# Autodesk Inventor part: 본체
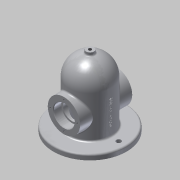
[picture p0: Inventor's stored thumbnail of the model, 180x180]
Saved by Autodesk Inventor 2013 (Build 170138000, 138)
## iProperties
Created: 2019-11
Part Number: 본체
Material: 알루미늄 6061
Document SubType Name: Modeling
Designer: Administrator
Density: 2.71 g/cm^3
Mass: 1186.55 g
Surface Area: 921.221 cm^2
Volume: 437.841 cm^3
Author: Administrator
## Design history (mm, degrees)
sketch "스케치1"
  geometry: C1 r 40 at (0, 0); 1 further point
  constraints: 1 centre point, 1 coincident
  dimensions: "d0" = 80 diameter of C1
extrude "돌출1" new body sketch "스케치1" distance "d2" = 90; taper "d3" = 0 deg
sketch "스케치2"
  geometry: L1 (40, 90)-(-40, 90) reference; L2 (0, 90)-(0, 130); L3 (-40, 90)-(0, 90); A1 r 40 centre (0, 90) between (0, 130) and (-40, 90); 1 further point
  constraints: 4 end point, 2 point on circle, 1 centre point, 1 coincident, 1 collinear, 1 midpoint, 1 perpendicular
revolve "회전1" sketch "스케치2" stored, may be unused: angle "d10" = 90 deg
sketch "스케치3"
  geometry: C1 r 40 at (0, 0) reference; C2 r 30 at (0, 0)
  constraints: 1 centre point, 1 coincident
  dimensions: "d11" = 60 diameter of C2
extrude "돌출2" cut sketch "스케치3" distance "d13" = 90; taper "d14" = 0 deg
sketch "스케치4"
  geometry: L1 (40, 90)-(40, 0) reference; L2 (40, 0)-(30, 0) reference; L3 (30, 0)-(30, 90) reference; L4 (30, 90)-(-30, 90) reference; L5 (-30, 90)-(-30, 0) reference; L6 (-30, 0)-(-40, 0) reference; L7 (-40, 0)-(-40, 90) reference; L8 (30, 90)-(-30, 90) reference; L9 (0, 90)-(0, 120); L10 (-30, 90)-(0, 90); A1 r 40 centre (0, 90) between (40, 90) and (0, 130) reference; A2 r 40 centre (0, 90) between (0, 130) and (-40, 90) reference; A3 r 30 centre (0, 90) between (0, 120) and (-30, 90); 1 further point
  constraints: 4 end point, 2 point on circle, 1 centre point, 1 coincident, 1 collinear, 1 perpendicular
revolve "회전2" sketch "스케치4" stored, may be unused: angle "d15" = 90 deg
sketch "스케치5"
  geometry: C1 r 70 at (0, 0); 1 further point
  constraints: 1 centre point, 1 coincident
  dimensions: "d16" = 140 diameter of C1
extrude "돌출3" join sketch "스케치5" distance "d18" = 10; taper "d19" = 0 deg
sketch "스케치6"
  geometry: C1 r 70 at (0, 0) reference; C2 r 70 at (0, 0) reference; C3 r 4.5 at (55, 0); C4 r 4.5 at (-55, 0); A1 r 55 centre (0, 0) between (55, 0) and (-55, 0)
  constraints: 3 centre point, 2 horizontal alignment, 2 point on circle, 1 coincident, 1 equal radius
  dimensions: "d20" = 110 diameter of A1; "d22" = 9 diameter of C3
extrude "돌출4" cut sketch "스케치6" stored distance "d23" = 10; taper "d24" = 0 deg
node "작업 평면1"
sketch "스케치7"
  geometry: C1 r 31 at (0, 50); 1 further point
  constraints: 1 centre point, 1 vertical alignment
  dimensions: "d26" = 62 diameter of C1; "d28" = 50 distance of C1.centre point (0, 0)
extrude "돌출5" join sketch "스케치7" stored distance "d29" = 10; taper "d30" = 0 deg
node "작업 평면2"
sketch "스케치8"
  geometry: C1 r 31 at (0, 50); 1 further point
  constraints: 1 centre point, 1 vertical alignment
  dimensions: "d32" = 62 diameter of C1; "d34" = 50 distance of C1.centre point (0, 0)
extrude "돌출6" join sketch "스케치8" stored distance "d35" = 10; taper "d36" = 0 deg
sketch "스케치9"
  geometry: C1 r 31 at (0, 0) reference; C2 r 20 at (0, 0); 1 further point
  constraints: 1 centre point, 1 coincident
  dimensions: "d37" = 40 diameter of C2
extrude "돌출7" cut sketch "스케치9" distance "d39" = 15; taper "d40" = 0 deg
fillet "모깎기1" dims "d41" = 0.3
sketch "스케치10"
  geometry: C1 r 19.7 at (0, 0) reference; C2 r 16.5 at (0, 0); 1 further point
  constraints: 1 centre point, 1 coincident
  dimensions: "d42" = 33 diameter of C2
extrude "돌출8" cut sketch "스케치10" stored distance "d44" = 15; taper "d45" = 0 deg
sketch "스케치11"
  geometry: C1 r 31 at (0, 0) reference; C2 r 20 at (0, 0); 1 further point
  constraints: 1 centre point, 1 coincident
  dimensions: "d46" = 40 diameter of C2
extrude "돌출9" cut sketch "스케치11" distance "d48" = 15; taper "d49" = 0 deg
fillet "모깎기2" dims "d50" = 0.3
sketch "스케치12"
  geometry: C1 r 19.7 at (0, 0) reference; C2 r 16.5 at (0, 0); 1 further point
  constraints: 1 centre point, 1 coincident
  dimensions: "d51" = 33 diameter of C2
extrude "돌출10" cut sketch "스케치12" stored distance "d53" = 15; taper "d54" = 0 deg
sketch "스케치13" dims "d55" = 52
  geometry: C1 r 20 at (0, 0) reference; C2 r 31 at (0, 0) reference; 6 further points
  constraints: 2 vertical alignment, 1 coincident, 7 other
  dimensions: "d59" = 360 deg dimension on C1.centre point (0, 26) (derived)
hole "구멍1" sketch "스케치13" at (0, 26), (-26, 0), (0, -26), (26, 0) diameter "d61" = 3.242; stored, may be unused: countersink angle "d65" = 90 deg, drill point angle "d67" = 118 deg; dims "d62" = 8, "d63" = 4, "d64" = 2, "d66" = 10
sketch "스케치14" dims "d68" = 52
  geometry: C1 r 20 at (0, 0) reference; C2 r 31 at (0, 0) reference; 6 further points
  constraints: 2 vertical alignment, 1 coincident, 7 other
  dimensions: "d72" = 360 deg dimension on C1.centre point (0, 26) (derived)
hole "구멍2" sketch "스케치14" at (0, 26), (-26, 0), (0, -26), (26, 0) diameter "d74" = 3.242; stored, may be unused: countersink angle "d78" = 90 deg, drill point angle "d80" = 118 deg; dims "d75" = 8, "d76" = 4, "d77" = 2, "d79" = 10
node "작업 평면3"
sketch "스케치15"
  geometry: C1 r 7.5 at (0, 0); 1 further point
  constraints: 1 centre point, 1 coincident
  dimensions: "d82" = 15 diameter of C1
extrude "돌출11" join sketch "스케치15" stored distance "d84" = 15; taper "d85" = 0 deg
sketch "스케치16"
  geometry: C1 r 7.5 at (0, 0) reference; C2 r 3 at (0, 0)
  constraints: 1 centre point, 1 coincident
  dimensions: "d86" = 6 diameter of C2
extrude "돌출12" cut sketch "스케치16" stored distance "d88" = 15; taper "d89" = 0 deg
feature "스레드1" dims "d90" = 10, "d91" = 0
node "작업 평면4"
sketch "스케치17"
  geometry: L1 (-70, 0)-(70, 0) reference; 4 further points
  constraints: 1 coincident, 1 midpoint, 1 vertical alignment, 1 other
  dimensions: "d92" = 50 distance from line of point (0, 50) L1
feature "엠보싱1" sketch "스케치17" dims "d93" = 0.5, "d94" = 0
fillet "모깎기3" dims "d95" = 3
chamfer "모따기1" distance "d96" = 1; stored, may be unused: second distance "d97" = 2, angle "d98" = 45 deg
chamfer "모따기2" distance "d99" = 1; stored, may be unused: second distance "d100" = 2, angle "d101" = 45 deg
sketch "스케치20"
  geometry: C1 r 70 at (0, 0) reference; C2 r 30 at (0, 0)
  constraints: 1 centre point, 1 coincident
  dimensions: "d108" = 60 diameter of C2
extrude "돌출15" cut sketch "스케치20" distance "d110" = 15; taper "d111" = 0 deg
node "솔리드1"
node "절단 모서리 투영1"
other parameters: "d81" = 135
